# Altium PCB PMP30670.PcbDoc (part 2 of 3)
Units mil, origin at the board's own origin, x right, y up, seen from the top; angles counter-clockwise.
Board outline 5900 x 3950 mil, 4 copper layers (Top Layer, GND, Signal Layer, Bottom Layer), stack 79.834 mil thick; 198 components, 106 nets, 638 pads, 723 vias.
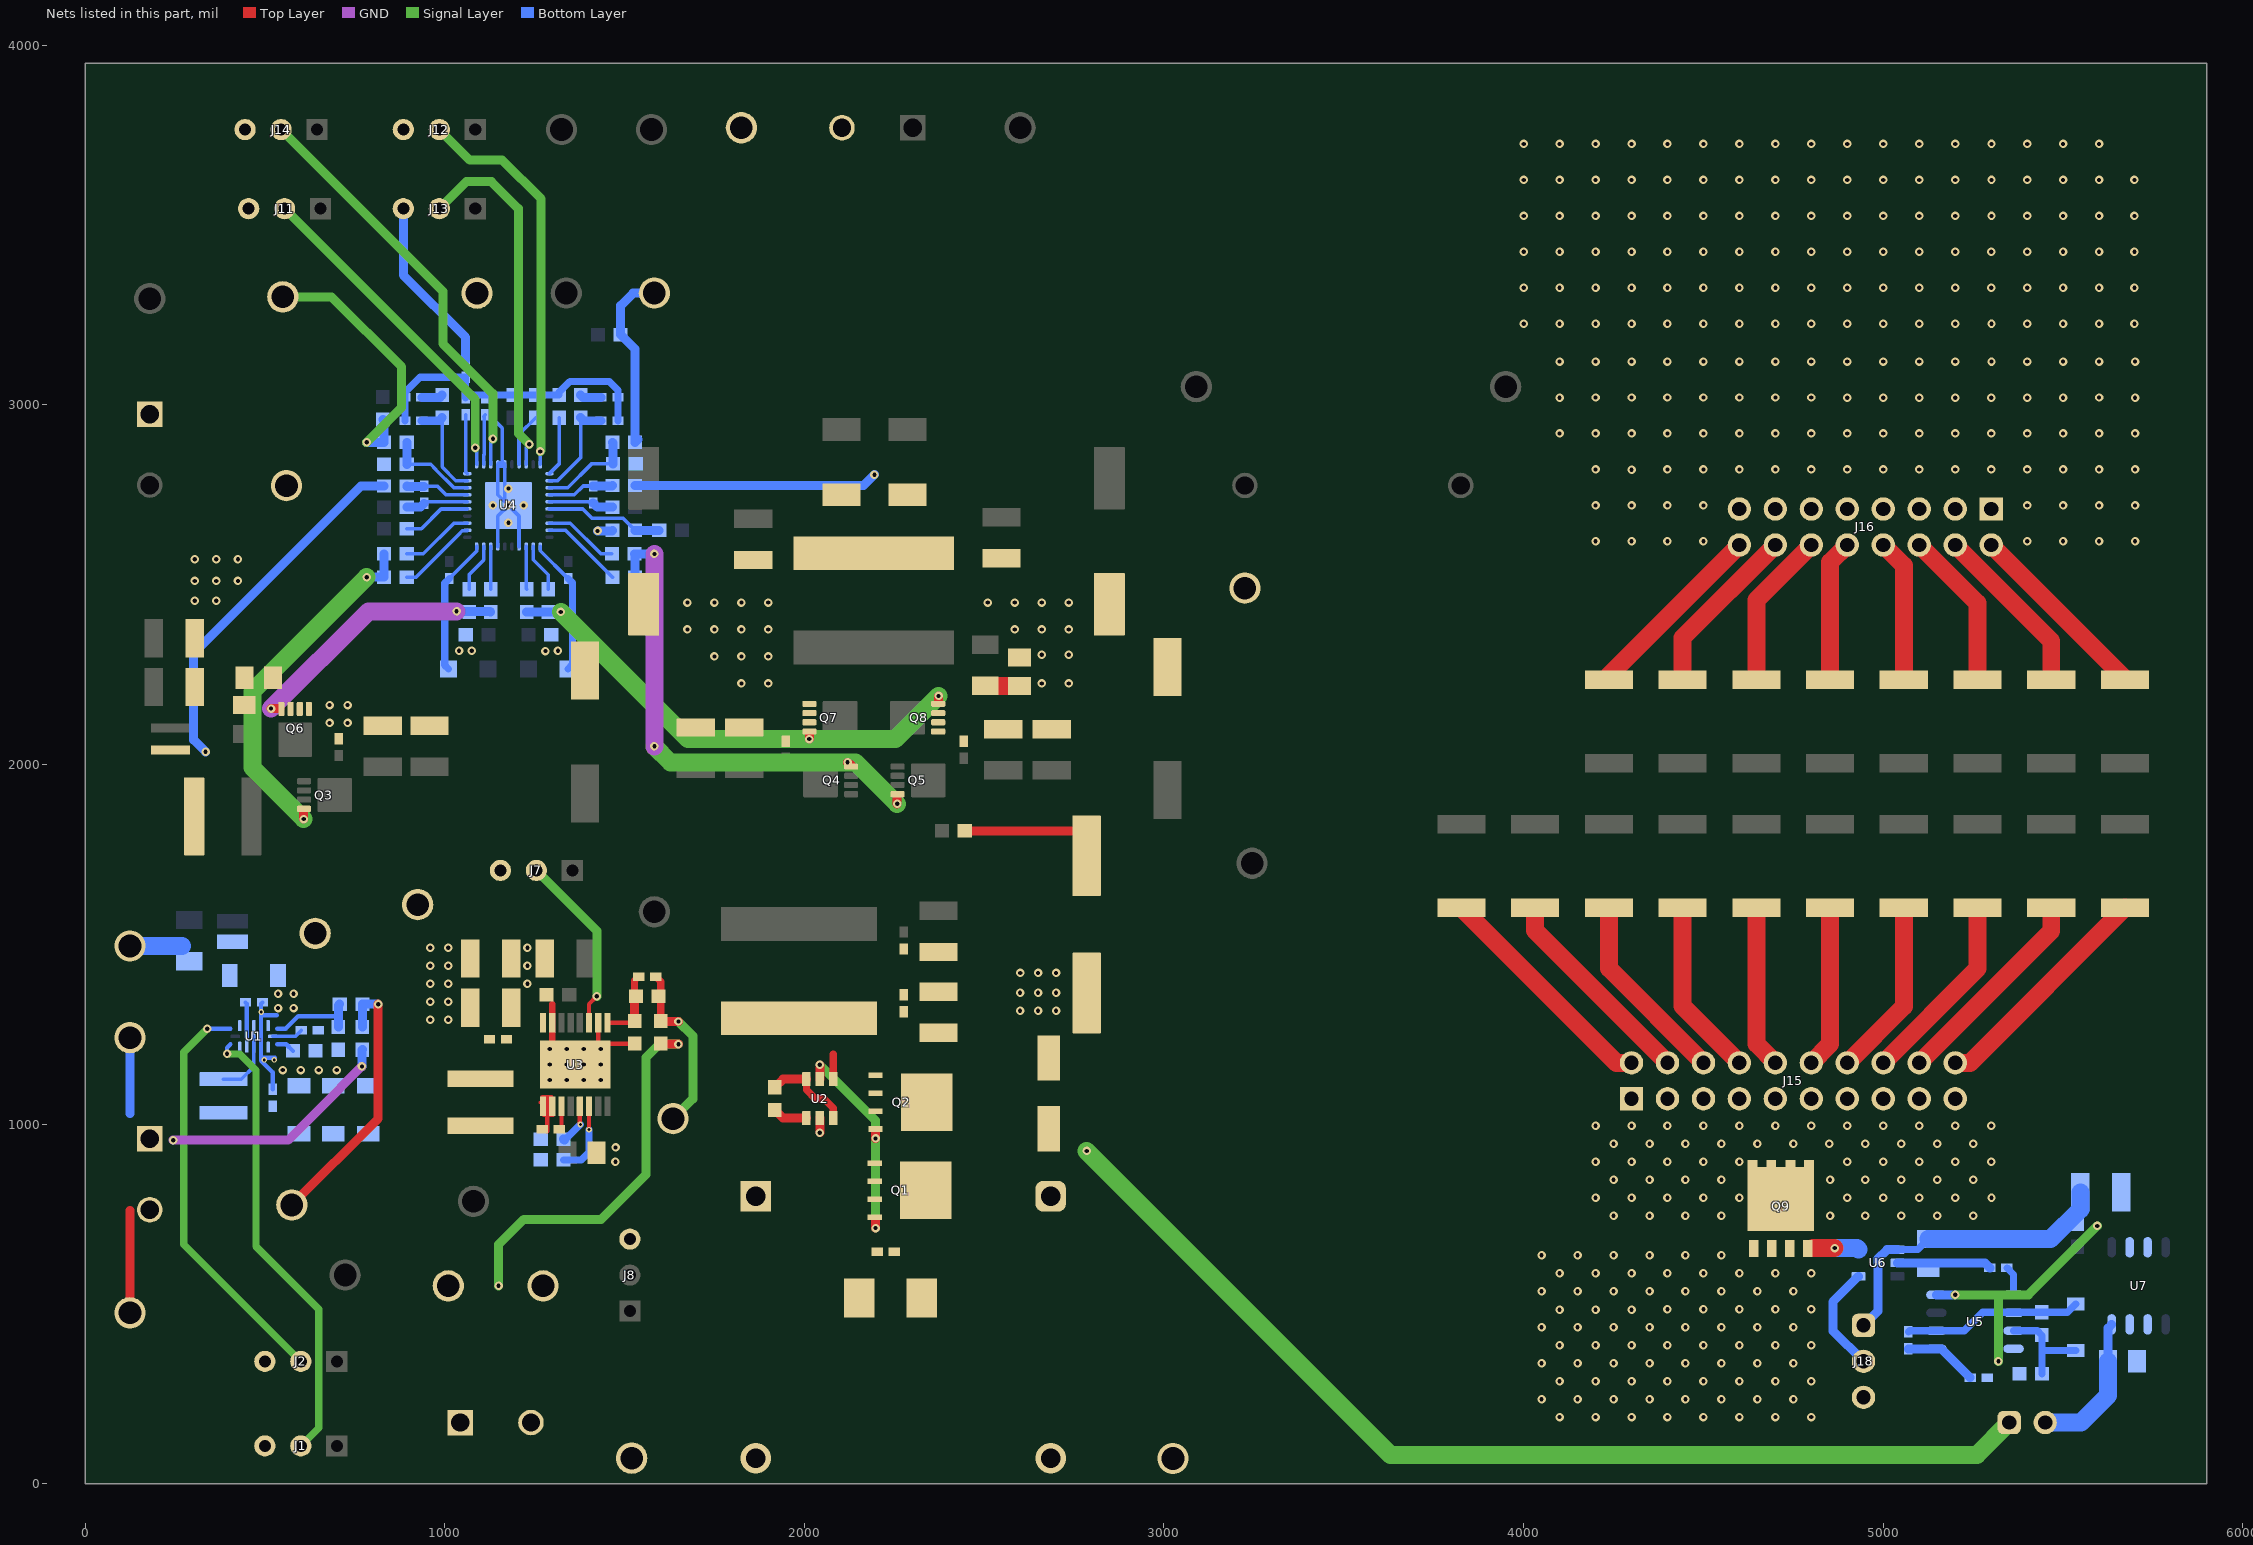
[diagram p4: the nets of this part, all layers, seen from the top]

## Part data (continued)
C40 C42: library part CMP-0008253-2, "CAP, CERM, 2200 pF, 250 V, +/- 10%, X7R, 0805", Cap_Case=0805, Manufacturer=MuRata, Supplier Part Number 1=490-3529-1-ND, TempCo=X7R, Tolerance_%=10%, Value1=Unknown, Value2=250V, ValueDisplayed=2200pF
C43: library part CMP-0007373-4, "CAP, CERM, 0.47 uF, 10 V, +/- 10%, X7R, 0603", Cap_Case=0603, Manufacturer=MuRata, Supplier Part Number 1=GRM188R71A474KA61D-ND, TempCo=X7R, Tolerance_%=10%, Value1=Unknown, Value2=10V, ValueDisplayed=0.47uF
C44 C45 C46: library part CMP-0007499-4, "CAP, CERM, 2.2 uF, 16 V, +/- 10%, X7R, 0603", Cap_Case=0603, Manufacturer=MuRata, Supplier Part Number 1=81-GRM188Z71C225KE3D, TempCo=X7R, Tolerance_%=10%, Value1=Unknown, Value2=16V, ValueDisplayed=2.2uF
C47 C48: library part CMP-0006641-2, "CAP, CERM, 0.1 uF, 16 V, +/- 10%, X7R, 0402", Cap_Case=0402, Manufacturer=MuRata, Supplier Part Number 1=490-3261-1-ND, TempCo=X7R, Tolerance_%=10%, Value1=Unknown, Value2=16V, ValueDisplayed=0.1uF
C49 C50: library part CMP-0006704-2, "CAP, CERM, 2200 pF, 100 V, +/- 10%, X7R, 0402", Cap_Case=0402, Manufacturer=MuRata, Supplier Part Number 1=GRM155R72A222KA01D-ND, TempCo=X7R, Tolerance_%=10%, Value1=Unknown, Value2=100V, ValueDisplayed=2200pF
C51: library part CMP-0006410-2, "CAP, CERM, 100 pF, 50 V, +/- 5%, C0G/NP0, 0402", Cap_Case=0402, Manufacturer=MuRata, Supplier Part Number 1=81-GRM1555C1H101JA1D, TempCo=C0G/NP0, Tolerance_%=5%, Value1=Unknown, Value2=50V, ValueDisplayed=100pF
C52: library part CMP-0006632-2, "CAP, CERM, 0.033 uF, 10 V, +/- 10%, X7R, 0402", Cap_Case=0402, Manufacturer=MuRata, Supplier Part Number 1=490-1315-1-ND, TempCo=X7R, Tolerance_%=10%, Value1=Unknown, Value2=10V, ValueDisplayed=0.033uF
C53: library part CMP-0006636-2, "CAP, CERM, 0.068 uF, 10 V, +/- 10%, X7R, 0402", Cap_Case=0402, Manufacturer=MuRata, Supplier Part Number 1=GRM155R71A683KA01D-ND, TempCo=X7R, Tolerance_%=10%, Value1=Unknown, Value2=10V, ValueDisplayed=0.068uF
C54: library part CMP-0007371-4, "CAP, CERM, 0.33 uF, 10 V, +/- 10%, X7R, 0603", Cap_Case=0603, Manufacturer=MuRata, Supplier Part Number 1=GRM188R71A334KA61D-ND, TempCo=X7R, Tolerance_%=10%, Value1=Unknown, Value2=10V, ValueDisplayed=0.33uF
C55: library part CMP-0006691-2, "CAP, CERM, 470 pF, 50 V, +/- 10%, X7R, 0402", Cap_Case=0402, Manufacturer=MuRata, Supplier Part Number 1=490-1300-1-ND, TempCo=X7R, Tolerance_%=10%, Value1=Unknown, Value2=50V, ValueDisplayed=470pF
C59: library part CMP-0008350-2, "CAP, CERM, 1 uF, 50 V, +/- 10%, X7R, 0805", Cap_Case=0805, Manufacturer=MuRata, Supplier Part Number 1=490-4736-1-ND, TempCo=X7R, Tolerance_%=10%, Value1=Unknown, Value2=50V, ValueDisplayed=1uF
C60: library part CMP-0009223-2, "CAP, CERM, 22 uF, 16 V, +/- 20%, X7R, 1210", Cap_Case=1210, Manufacturer=MuRata, Supplier Part Number 1=490-4740-1-ND, TempCo=X7R, Tolerance_%=20%, Value1="0.003 ohm", Value2=16V, ValueDisplayed=22uF
C64: library part CMP-0008320-2, "CAP, CERM, 4.7 uF, 10 V, +/- 10%, X7R, 0805", Cap_Case=0805, Manufacturer=MuRata, Supplier Part Number 1=GRM21BR71A475KA73L-ND, TempCo=X7R, Tolerance_%=10%, Value1=Unknown, Value2=10V, ValueDisplayed=4.7uF
"CAUTION! HOT SURFACE!1": library part CMP-0074837-1, "IEC 61010-1 Hot Surface Warning"
D1: library part CMP-0005564-3, "Diode, TVS, Bi, 33 V, SMB", Manufacturer="Diodes Inc.", Value1=600W
D2 D3: library part CMP-0028377-2, "Diode, Schottky, 60 V, 1 A, SOD-123F", Manufacturer=Nexperia, Value1=1A, Value2=0.57V
D4: library part CMP-0076920-2, "Diode, Switching, 100 V, 0.15 A, SOD-123FL", Manufacturer=Vishay-Semiconductor, Value1=0.15A, Value2=1.2V
J1 J2 J7 J8 J11 J12 J13 J14: library part CMP-0055086-1, "Header, 100mil, 3x1, TH", Manufacturer=Mill-Max, Supplier Part Number 1=ED7203-ND
J3 J6 J9 J10: library part CMP-0054828-1, "Terminal Block, 5 mm, 2x1, Tin, TH", Manufacturer="Wurth Elektronik", Supplier Part Number 1=732-2026-ND
J4: library part CMP-0055403-2, "TEST SOCKET, PCB, 4MM, RED", Manufacturer=Hirschmann, Supplier Part Number 1=06WX5875
J5: library part CMP-0055402-3, "TEST SOCKET, PCB, 4MM, BLACK", Color=Black, Manufacturer=Hirschmann, Supplier Part Number 1=06WX5874
J15: library part CMP-0075421-2, "Header, 100mil, 10x2, Gold, TH", Color=Black, Current_A=6.3A, Manufacturer=Samtec, Supplier Part Number 1=SAM1028-10-ND, Voltage_V=550V
J16: library part CMP-0075418-1, "Header, 100mil, 8x2, Gold, TH", Color=Black, Current_A=6.3A, Manufacturer=Samtec, Supplier Part Number 1=SAM1028-08-ND, Voltage_V=550V
J17: library part CMP-0075405-2, "Header, 100mil, 2x1, Gold, TH", Color=Black, Current_A=6.3A, Manufacturer=Samtec, Supplier Part Number 1=SAM1029-02-ND, Voltage_V=550V
J18: library part CMP-0075407-2, "Header, 100mil, 3x1, Gold, TH", Color=Black, Current_A=6.3A, Manufacturer=Samtec, Supplier Part Number 1=SAM1029-03-ND, Voltage_V=550V
L1: library part CMP-0061169-1, "Inductor, Shielded, Composite, 200 nH, 2.8 A, 0.02 ohm, SMD", Manufacturer=Coilcraft, Value1="0.02 ohm", Value2=2.8A, ValueDisplayed=200nH
L2: library part CMP-0061081-2, "Inductor, Shielded, Composite, 560 nH, 11.3 A, 0.008 ohm, AEC-Q200 Grade 1, SMD", Manufacturer=Coilcraft, Value1="0.008 ohm", Value2=11.3A, ValueDisplayed=560nH
L3: library part CMP-0060965-1, "Inductor, Shielded, Composite, 4.7 uH, 14 A, 0.0098 ohm, AEC-Q200 Grade 1, SMD", Manufacturer=Coilcraft, Supplier Part Number 1=994-XAL1060-472MEB, Value1="0.0098 ohm", Value2=14A, ValueDisplayed=4.7uH
L4: library part CMP-0061001-2, "Inductor, Shielded, Composite, 2.2 µH, 9.2 A, 0.01 ohm, AEC-Q200 Grade 1, SMD", Manufacturer=Coilcraft, PartNumber=XAL5030-222MEB, Value1="0.01 ohm", Value2=9.2A, ValueDisplayed=2.2uH
L5: library part CMP-0061652-3, "Inductor, Shielded, Composite, 15 µH, 5.8 A, 0.04375 ohm, AEC-Q200 Grade 1, SMD", Manufacturer=Coilcraft, Value1="0.04375 ohm", Value2=5.8A, ValueDisplayed=15uH
L6: library part CMP-0060947-1, "Inductor, Shielded, Composite, 2.2 uH, 32 A, 0.00255 ohm, SMD", Manufacturer=Coilcraft, Supplier Part Number 1=994-XAL1010-222MEB, Value1="0.00255 ohm", Value2=32A, ValueDisplayed=2.2uH
Q1 Q2: library part CMP-0000880-1, "MOSFET, N-CH, 60 V, 30 A, AEC-Q101, PowerPAK_SO-8L", Alternate Manufacturer=None, Manufacturer=Vishay-Siliconix, Value1=0.01, Value2="18 nC"
Q3 Q4 Q5 Q6 Q7 Q8: library part CMP-0080660-1, "MOSFET, N-CH, 40 V, 40 A, AEC-Q101, SON-8", Alternate Manufacturer=None, Manufacturer="Infineon Technologies", PartNumber=IPZ40N04S5L4R8ATMA1, Supplier Part Number 1=IPZ40N04S5L4R8ATMA1CT-ND, Value1="0.0067 ohm", Value2="22 nC"
Q9: library part CMP-0000690-1, "MOSFET, N-CH, 40 V, 49 A, PG-TDSON-8", Alternate Manufacturer=None, Manufacturer="Infineon Technologies", Supplier Part Number 1="BSC093N04LS GCT-ND", Value1=0.013, Value2="18 nC"
R1: library part CMP-0018748-3, "RES, 0, 5%, 0.25 W, AEC-Q200 Grade 0, 1206", Manufacturer=Panasonic, Power_W=250mW, Supplier Part Number 1=P0.0ECT-ND, TempCo="600 ppm/C", Tolerance_%=5%, Value2=0.25W, Value_Code=0000, ValueDisplayed=DNP
R2 R7 R26 R27 R31 R32: library part CMP-0022448-4, "RES, 49.9, 1%, 0.1 W, AEC-Q200 Grade 0, 0603", Manufacturer=Vishay-Dale, Power_W=100mW, Supplier Part Number 1=541-49.9HCT-ND, TempCo="100 ppm/C", Tolerance_%=1%, Value2=0.1W, Value_Code=49R9, ValueDisplayed=49.9
R3: library part CMP-0022369-4, "RES, 39.2 k, 1%, 0.1 W, AEC-Q200 Grade 0, 0603", Manufacturer=Vishay-Dale, Power_W=100mW, Supplier Part Number 1=541-39.2KHCT-ND, TempCo="100 ppm/C", Tolerance_%=1%, Value2=0.1W, Value_Code=39k2, ValueDisplayed=39.2k
R4: library part CMP-0022665-4, "RES, 9.09 k, 1%, 0.1 W, AEC-Q200 Grade 0, 0603", Manufacturer=Vishay-Dale, Power_W=100mW, Supplier Part Number 1=541-9.09KHCT-ND, TempCo="100 ppm/C", Tolerance_%=1%, Value2=0.1W, Value_Code=9k09, ValueDisplayed=9.09k
R5: library part CMP-0022438-4, "RES, 47.0 k, 1%, 0.1 W, AEC-Q200 Grade 0, 0603", Manufacturer=Vishay-Dale, Power_W=100mW, Supplier Part Number 1=541-47.0KHCT-ND, TempCo="100 ppm/C", Tolerance_%=1%, Value2=0.1W, Value_Code=47k0, ValueDisplayed=47.0k
R6: library part CMP-0022722-1, "RES, 0.12, 1%, 0.1 W, 0603", Manufacturer=Panasonic, Power_W=100mW, Supplier Part Number 1=P.12AJCT-ND, TempCo="300 ppm/C", Tolerance_%=1%, Value2=0.1W, Value_Code=R120, ValueDisplayed=0.12
R8: library part CMP-0022434-4, "RES, 46.4 k, 1%, 0.1 W, AEC-Q200 Grade 0, 0603", Manufacturer=Vishay-Dale, Power_W=100mW, Supplier Part Number 1=541-46.4KHCT-ND, TempCo="100 ppm/C", Tolerance_%=1%, Value2=0.1W, Value_Code=46k4, ValueDisplayed=46.4k
R9: library part CMP-0022602-4, "RES, 7.68 k, 1%, 0.1 W, AEC-Q200 Grade 0, 0603", Manufacturer=Vishay-Dale, Power_W=100mW, Supplier Part Number 1=541-7.68KHCT-ND, TempCo="100 ppm/C", Tolerance_%=1%, Value2=0.1W, Value_Code=7k68, ValueDisplayed=7.68k
R10 R37 R38: library part CMP-0021998-4, "RES, 10.0 k, 1%, 0.1 W, AEC-Q200 Grade 0, 0603", Manufacturer=Vishay-Dale, Power_W=100mW, Supplier Part Number 1=541-10.0KHCT-ND, TempCo="100 ppm/C", Tolerance_%=1%, Value2=0.1W, Value_Code=10k0, ValueDisplayed=10.0k
R11: library part CMP-0022204-4, "RES, 20.0 k, 1%, 0.1 W, AEC-Q200 Grade 0, 0603", Manufacturer=Vishay-Dale, Power_W=100mW, Supplier Part Number 1=541-20.0KHCT-ND, TempCo="100 ppm/C", Tolerance_%=1%, Value2=0.1W, Value_Code=20k0, ValueDisplayed=20.0k
R12: library part CMP-0015211-2, "RES, 0.013, 1%, 1 W, 0612", Manufacturer="Susumu Co Ltd", Power_W=1W, Supplier Part Number 1=PRL1632.013FCT-ND, TempCo="200 ppm/C", Tolerance_%=1%, Value_Code=R013, ValueDisplayed=0.013
R13 R15: library part CMP-0016512-2, "RES, 0.005, 1%, 1.5 W, 2010", Manufacturer="Stackpole Electronics Inc", Power_W=1.5W, Supplier Part Number 1=CSNL2010FT5L00CT-ND, TempCo="50 ppm/C", Tolerance_%=1%, Value_Code=5L000, ValueDisplayed=0.005
R14: library part CMP-0020487-2, "RES, 1.0, 5%, 0.125 W, 0805", Manufacturer=Vishay-Dale, Power_W=125mW, Supplier Part Number 1=541-1.0ACT-ND, TempCo="200 ppm/C", Tolerance_%=5%, Value2=0.125W, Value_Code=1R00, ValueDisplayed=DNP
R16: library part CMP-0016745-3, "RES, 1.00, 1%, 0.25 W, AEC-Q200 Grade 0, 1206", Manufacturer=Vishay-Dale, Power_W=250mW, Supplier Part Number 1=53K1855, TempCo="100 ppm/C", Tolerance_%=1%, Value2=0.25W, Value_Code=1R00, ValueDisplayed=DNP
R17: library part CMP-0022170-4, "RES, 1.00, 1%, 0.1 W, AEC-Q200 Grade 0, 0603", Manufacturer=Vishay-Dale, Power_W=100mW, Supplier Part Number 1=52K8059, TempCo="100 ppm/C", Tolerance_%=1%, Value2=0.1W, Value_Code=1R00, ValueDisplayed=1.00
R18 R19 R20 R21 R22 R23 R24 R25 R28 R29 R30: library part CMP-0025874-1, "RES, 0, 5%, 0.1 W, 0603", Manufacturer=Panasonic, Power_W=100mW, Supplier Part Number 1=P0.0GCT-ND, TempCo="600 ppm/C", Tolerance_%=5%, Value2=0.1W, Value_Code=0000, ValueDisplayed=0
R33: library part CMP-0022585-4, "RES, 73.2 k, 1%, 0.1 W, AEC-Q200 Grade 0, 0603", Manufacturer=Vishay-Dale, Power_W=100mW, Supplier Part Number 1=541-73.2KHCT-ND, TempCo="100 ppm/C", Tolerance_%=1%, Value2=0.1W, Value_Code=73k2, ValueDisplayed=73.2k
R34: library part CMP-0022430-4, "RES, 45.3 k, 1%, 0.1 W, AEC-Q200 Grade 0, 0603", Manufacturer=Vishay-Dale, Power_W=100mW, Supplier Part Number 1=541-45.3KHCT-ND, TempCo="100 ppm/C", Tolerance_%=1%, Value2=0.1W, Value_Code=45k3, ValueDisplayed=45.3k
R35: library part CMP-0022515-4, "RES, 5.90 k, 1%, 0.1 W, AEC-Q200 Grade 0, 0603", Manufacturer=Vishay-Dale, Power_W=100mW, Supplier Part Number 1=541-5.90KHCT-ND, TempCo="100 ppm/C", Tolerance_%=1%, Value2=0.1W, Value_Code=5k90, ValueDisplayed=5.90k
R36: library part CMP-0022044-4, "RES, 13.7 k, 1%, 0.1 W, AEC-Q200 Grade 0, 0603", Manufacturer=Vishay-Dale, Power_W=100mW, Supplier Part Number 1=541-13.7KHCT-ND, TempCo="100 ppm/C", Tolerance_%=1%, Value2=0.1W, Value_Code=13k7, ValueDisplayed=13.7k
R39: library part CMP-0022494-4, "RES, 54.9 k, 1%, 0.1 W, AEC-Q200 Grade 0, 0603", Manufacturer=Vishay-Dale, Power_W=100mW, Supplier Part Number 1=541-54.9KHCT-ND, TempCo="100 ppm/C", Tolerance_%=1%, Value2=0.1W, Value_Code=54k9, ValueDisplayed=54.9k
R40: library part CMP-0014307-3, "RES, 0.01, 1%, 3 W, 15.2x1.0x25.4", Manufacturer="TT Electronics/IRC", Power_W=3W, Supplier Part Number 1=989-1088-ND, TempCo="20 ppm/C", Tolerance_%=1%, Value_Code=R010, ValueDisplayed=0.01
R41 R42 R43 R44 R45 R46 R47 R48 R49 R50: library part CMP-0015940-2, "RES, 30, 5%, 1 W, AEC-Q200 Grade 0, 2512", Manufacturer=Vishay-Dale, Power_W=1W, Supplier Part Number 1=541-30XCT-ND, TempCo="200 ppm/C", Tolerance_%=5%, Value_Code=30R0, ValueDisplayed=30
R51 R52 R53 R54 R55 R56 R57 R58: library part CMP-0015453-3, "RES, 12.1, 1%, 1 W, AEC-Q200 Grade 0, 2512", Manufacturer=Vishay-Dale, Power_W=1W, Supplier Part Number 1=541-12.1AFCT-ND, TempCo="100 ppm/C", Tolerance_%=1%, Value_Code=12R1, ValueDisplayed=12.1
R59 R60: library part CMP-0022581-4, "RES, 71.5 k, 1%, 0.1 W, AEC-Q200 Grade 0, 0603", Manufacturer=Vishay-Dale, Power_W=100mW, Supplier Part Number 1=541-71.5KHCT-ND, TempCo="100 ppm/C", Tolerance_%=1%, Value2=0.1W, Value_Code=71k5, ValueDisplayed=71.5k
R61: library part CMP-0025743-1, "RES, 1.0, 5%, 0.1 W, 0603", Manufacturer=Vishay-Dale, Power_W=100mW, Supplier Part Number 1=541-1.0GCT-ND, TempCo="200 ppm/C", Tolerance_%=5%, Value2=0.1W, Value_Code=1R00, ValueDisplayed=1.0
TP1 TP2 TP6 TP9 TP10 TP15 TP17 TP19 TP20: library part CMP-0055147-1, "Test Point, Multipurpose, Red, TH", Color=Red, Manufacturer=Keystone, Supplier Part Number 1=36-5010-ND
TP3 TP7 TP8 TP11 TP14 TP16 TP18 TP25 TP26: library part CMP-0055148-1, "Test Point, Multipurpose, Black, TH", Color=Black, Manufacturer=Keystone, Supplier Part Number 1=36-5011-ND
TP4 TP12 TP23 TP24: library part CMP-0055151-1, "Test Point, Multipurpose, Yellow, TH", Color=Yellow, Manufacturer=Keystone, Supplier Part Number 1=36-5014-ND
TP5 TP13 TP21 TP22: library part CMP-0055149-1, "Test Point, Multipurpose, White, TH", Color=White, Manufacturer=Keystone, Supplier Part Number 1=36-5012-ND
TP27 TP28: library part CMP-0055150-1, "Test Point, Multipurpose, Orange, TH", Color=Orange, Manufacturer=Keystone, Supplier Part Number 1=36-5013-ND
U1: library part CMP-0082642-1, "Automotive Low Input Voltage, Adjustable-Frequency Step-down Converter, RWY0009A (VQFN-HR-9)", Alternate Manufacturer="Texas Instruments", Operating Temperature Range="-40 to 150 C", Rating=Automotive
U2: library part CMP-0013281-4, "Low Iq Always ON Smart Diode Controller, DBV0006A (SOT-23-6)", Alternate Manufacturer="Texas Instruments", Alternate PartNumber=LM74700QDBVTQ1
U3: library part CMP-0080079-4, "3.5-V to 36-V, 3.5-A Synchronous Step-Down Voltage Regulator with Spread Spectrum, PWP0016D (TSSOP-16)", Alternate Manufacturer="Texas Instruments", Rating=Automotive
U4: library part CMP-0079128-2, "3.5-V to 65-V Low IQ, Dual Synchronous Buck DC-DC Controller, RWG0040A (VQFNP-40)", Alternate Manufacturer="Texas Instruments", Alternate PartNumber=LM5143QRWGTQ1, Operating Temperature Range="-40 to 125 C", Rating=Automotive
U5: library part CMP-0068883-1, "CMOS Timer, 8-pin Narrow SOIC, Pb-Free", Manufacturer="Texas Instruments", PackageTopMarking=NSZXTT*LMC*555CM, PowerWise=N
U6: library part CMP-0066947-1, "4A/4A Single Channel High-speed Low-side Gate Driver, DBV0005A (SOT-23-5)", Alternate Manufacturer="Texas Instruments", Alternate PartNumber=UCC27517DBVT
U7: library part CMP-0035296-1, "Single Output LDO, 150 mA, Fixed 5 V Output, 6 to 26 V Input, with Low IQ, 8-pin SOIC (D), 0 to 125 degC, Green (RoHS & no Sb/Br)", Manufacturer="Texas Instruments", Rating=Catalog

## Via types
v1: diameter 23.62, hole 11.81, Top Layer to Bottom Layer, tented both sides, 701 vias
v2: diameter 23.62, hole 11.81, Top Layer to Bottom Layer, 11 vias
v3: diameter 15.75, hole 7.87, Top Layer to Bottom Layer, tented both sides, 7 vias
v4: diameter 196.85, hole 118.11, Top Layer to Bottom Layer, 4 vias

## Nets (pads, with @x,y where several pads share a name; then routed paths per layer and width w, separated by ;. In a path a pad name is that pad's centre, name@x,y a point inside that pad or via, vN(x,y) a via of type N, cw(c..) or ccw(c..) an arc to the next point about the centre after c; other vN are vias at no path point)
1V1_SINGLE_BUCK: C1.1 C2.1 C3.1 C4.1 J3.1 L2.2 R2.2 TP1.1 | length 869
  GND w25: v1(245,955) 565,955 650,1040 v1(770,1160)
  Bottom Layer w20: v1(770,1160) v1@771.14,1161.14
  Bottom Layer w25: 125,1029.58 TP1.1@125,1240 ; v1(770,1160) 770,1205.43 R2.2@771.14,1206.57
3V3_SINGLE_BUCK: C19.1 C20.1 C21.1 J6.1 L4.2 R7.2 TP10.1 | length 1086.1
  Top Layer w25: R7.2@1600.67,1223.51 1602.33,1221.85 v1(1650,1221.85)
  Signal Layer w25: v1(1150,550) 1150,665 1220,735 1435,735 1559.44,859.44 1559.44,1184.44 1596.85,1221.85 v1(1650,1221.85)
  other v1: 960,1290 1010,1290 960,1340 1010,1340 960,1390 1010,1390 960,1440 1010,1440 960,1490 1010,1490
CS1_DUAL_BUCK: L5.1 R12.2 R26.2 | length 1009.4
  Bottom Layer w25: v1(335,2035) 302.13,2067.87 302.13,2308.62 767.49,2773.98 R26.2@831.57,2773.98
CS2_DUAL_BUCK: L6.2 R13.1 R15.1 R27.1 | length 677.9
  Bottom Layer w25: R27.1@1529.57,2775.35 2165,2775.35 v1(2195,2805.35)
DEMB_DUAL_BUCK: J14.2 U4.33 | length 1177.7
  Signal Layer w25: J14.2@545,3765 995,3315 995,3170 1134.33,3030.67 v1(1134.33,2905)
  Bottom Layer w10: U4.33@1128.03,2834.06 1128.03,2898.7 v1(1134.33,2905)
DITH_DUAL_BUCK: J13.2 U4.38 | length 1009
  Signal Layer w25: J13.2@985,3545 1060,3620 1130,3620 1205,3545 1205,2920 v1(1235,2890)
  Bottom Layer w10: U4.38@1226.46,2834.06 1226.46,2881.46 v1(1235,2890)
EN1_DUAL_BUCK: J11.2 U4.31 | length 932
  Signal Layer w25: J11.2@555,3545 1085,3015 v1(1085,2880)
  Bottom Layer w10: v1(1085,2880) 1088.66,2876.34 U4.31@1088.66,2834.06
EN2_DUAL_BUCK: J12.2 U4.40 | length 1101.7
  Signal Layer w25: J12.2@985,3765 1070,3680 1160,3680 1267.87,3572.13 1267.87,2872.05 v1(1265.83,2870)
  Bottom Layer w10: U4.40@1265.83,2834.06 v1(1265.83,2870)
EN_1V1_BUCK: J1.2 U1.8 | length 1267.7
  Signal Layer w20: v1(395,1195) 430,1195 475,1150 475,660 650,485 650,155 J1.2@600,105
  Bottom Layer w12: v1(395,1195) 395,1212.13 404.69,1221.81
EN_3V3_BUCK: J7.2 U3.11 | length 502.1
  Top Layer w12: U3.11@1401.46,1281.5 1401.46,1333.39 v1(1423.07,1355)
  Signal Layer w25: J7.2@1255,1705 1423.07,1536.93 v1(1423.07,1355)
FB1_DUAL_BUCK: R33.1 R37.2 U4.28 | length 256.9
  Bottom Layer w10: R37.2@894.57,2834.06 960.94,2834.06 975.2,2819.8 975.2,2819.53 1023.82,2770.91 1024.09,2770.91 1025.91,2769.09 U4.28@1063.07,2769.09
  Bottom Layer w25: R37.2@894.57,2834.06 R33.1@894.57,2895.35
FB2_DUAL_BUCK: R34.1 R38.2 U4.3 | length 264.7
  Bottom Layer w10: U4.3@1291.42,2769.09 1341.81,2769.09 1408.07,2835.35 R38.2@1468.07,2835.35
  Bottom Layer w25: R34.1@1466.57,2895.35 1468.07,2893.86 R38.2@1468.07,2835.35
GND: C1.2 C2.2 C3.2 C4.2 C5.2 C6.2 C7.2 C8.2 C10.2 C11.2 C12.2 C13.2 C14.2 C15.1 C17.2 C18.2 C19.2 C20.2 C21.2 C23.2 C24.2 C25.2 C26.2 C27.2 C28.2 C29.2 C30.2 C31.2 C32.2 C33.2 C34.2 C35.2 C36.2 C37.1 C38.2 C39.2 C40.2 C41.1 C42.2 C43.1 C44.2 C45.2 C46.2 C51.2 C52.2 C53.2 C54.2 C55.2 C56.2 C57.2 C58.2 C59.2 C60.2 C61.2 C62.2 C63.2 C64.2 D1.1 J1.3 J2.3 J3.2 J5.1 J5.2 J6.2 J7.3 J8.3 J9.1 J10.2 J11.3 J12.3 J14.3 J16.1 J16.3 J16.5 J16.7 J16.9 J16.11 J16.13 J16.15 J18.3 Q6.1 Q6.2 Q6.3 Q7.1 Q7.2 Q7.3 Q8.1 Q8.2 Q8.3 Q9.1 Q9.2 Q9.3 R4.1 R5.1 R9.1 R10.1 R11.1 R37.1 R38.1 R39.1 TP3.1 TP7.1 TP8.1 TP11.1 TP14.1 TP16.1 TP18.1 TP25.1 TP26.1 U1.4@489.33,1243.46 U2.2 U3.10 U3.15 U3.16 U3.17@1363.07,1165.35 U4.14 U4.17 U4.34 U4.35 U4.41 U5.1 U6.2 U7.2 U7.3 U7.6 U7.7 | length 3142.9
  Top Layer w12: U3.17@1363.07,1165.35 U3.17@1421.22,1223.51 ; U3.10@1427.05,1281.5 1427.05,1229.33 U3.17@1421.22,1223.51 ; R11.1@1528.07,1223.51 U3.17@1421.22,1223.51
  Top Layer w17.5: U3.17@1298.99,1230 1299.04,1281.5 1299.09,1333.6
  Top Layer w25: TP7.1@125,475 125,760 ; U3.17@1363.07,1165.35 v2(1386.69,1165.35) v1(1433.94,1165.35) ; v1(2043.07,975.71) U2.2@2043.07,1016.57
  Bottom Layer w10: 1140,3018.98 1140,2955 1160,2935 1160,2841.46 ; U4.17@1147.72,2605.71 1147.72,2690.35 v2(1177.24,2719.88) ; U4.34@1147.72,2834.06 1147.72,2749.41 U4.41@1167.4,2729.72 ; U4.35@1167.4,2834.06 U4.41@1167.4,2729.72 ; U4.14@1206.77,2605.71 1206.77,2690.35 v2(1177.24,2719.88) ; U4.41@1167.4,2729.72 v2(1177.24,2719.88)
  Bottom Layer w12: C6.2@493.27,1338.07 489.33,1334.13 489.33,1300 ; C1.2@521.81,1096.69 521.81,1143.54 489.33,1176.02 489.33,1185 ; v3@528.24,1184.32 490.02,1184.32 489.33,1185 ; 533.43,1302.61 491.94,1302.61 489.33,1300 ; 489.33,1185 U1.4@489.33,1243.46 489.33,1300
  Bottom Layer w20: C51.2@889.45,2955.35 C56.2@889.45,3020.35 889.45,3034.45 931.38,3076.38 C58.2@1058.07,3076.38 C52.2@1058.07,3018.98 1065.94,3026.85 C54.2@1318.07,3026.85 1318.07,3034.45 1348.03,3064.41 1457.6,3064.41 1481.69,3040.31 C57.2@1481.69,3020.35 C55.2@1481.69,2955.35 ; 1153,2834.06 1162,2834.06
  Bottom Layer w25: v1(1425,2649.09) 1465.32,2649.09 C44.2@1466.57,2650.35 ; U6.2@5039.13,613.62 5282.76,613.62 C63.2@5296.38,600 ; C62.2@5070,374.88 5147.6,374.88 U5.1@5147.72,375 5161.38,375 C61.2@5241.38,295
  other v1: 4100,185.16 4200,185 4300,185 4400,185 4500,185 4600.04,185 4700,185.16 4800,185.16 4050,235 4150,235 4250,235 4350,235 4450,235 4550,235 4650,235 4750,235 4100,285 4200,285 4300,285 4400,285 4500,285 4600.04,285 4700,285 4800,285 4050,335 4150,335 4250,335 4350,335 4450,335 4550,335 4650,335 4750,335 4100,385 4200,385 4300,385 4400,385 4500,385 4600.04,385 4700,385 4800,385 4050,435 4150,435 4250,435 4350,435 4450,435 4550,435 4650,435 4750,435 4100,483.53 4200,483.53 4300,483.53 4400,485 4500,485 4600.04,485 4700,485 4800,485 4050,535 4150,535 4250,535 4350,535 4450,535 4550,535 4650,535 4750,535 4100,585 4200,585 4300,585 4400,585 4500,585 4600,585 4700,585 4800,585 4050,634.83 4150,634.83 4250,635 4350,635 4450,635 4550,635 1474.84,895 1475,935 1292.2,1122.05 1433.94,1122.05 550,1150 600,1150 650,1150 700,1150 1292.2,1165.35 1292.2,1208.66 1433.94,1208.66 2600,1315 2650,1315 2700,1315 536.57,1322.52 580,1322.52 536.57,1362 580,1362 2600,1365 2650,1365 2700,1365 1230,1390 2600.69,1420 2650,1420 2700,1420 1230,1440 1230,1490 680,2115 730,2115 680,2165 730,2165 1825,2225 1900,2225 2660,2225 2735.36,2225 1750,2300 1825,2300 1900,2300 2660,2305 2735.36,2305 1280,2315 1040,2315.8 1075,2315.8 1315,2315.8 1675,2375 1750,2375 1825,2375 1900,2375 2585,2375 2660,2375 2735,2375 1675,2450 1750,2450 1825,2450 1900,2450 2510,2450 2585,2450 2660,2450 2735,2450 305,2455 365,2455 305,2510 365,2510 425,2510 305,2570 365,2570 425,2570 4200,2620 4300,2620 4400,2620 4500,2620 5400,2620 5500,2620 5600,2620 5700,2620 4200,2720 4300,2719.88 4400,2720 4500,2720 5400,2720 5500,2719.88 5600,2720 5700,2719.88 4300,2819.41 4200,2820 4400,2820 4500,2820 4600,2820 4700,2820 4800,2820 4900,2820 5000,2820 5100,2820 5200,2820 5300,2820 5400,2820 5500,2820 5600,2820 5700,2820 4100,2920 4200,2920 4300,2920 4400,2920 4500,2920 4600,2920 4700,2920 4800,2920 4900,2920 5000,2920 5100,2920 5200,2920 5300,2920 5400,2920 5500,2920 5600,2920 5700,2920 4100,3018.98 4900,3018.98 5000,3018.98 5100,3018.98 5200,3018.98 5300,3018.98 5400,3018.98 5500,3018.98 5700,3018.98 4200,3020 4300,3020 4400,3020 4500,3020 4600.04,3020 4700,3020 4800,3020 5600,3020 4100,3120 4200,3120 4300,3120 4400,3120 4500,3120 4600.04,3120 4700,3120 4800,3120 4900,3120 5000,3120 5100,3120 5200,3120 5300.88,3120 5400,3120 5500,3120 5600,3120 5700,3120 4000,3225 4100,3225 4200,3225 4300,3225 4400,3225 4500,3225 4600,3225 4700,3225 4800,3225 4900,3225 5000,3225 5100,3225 5200,3225 5300.88,3225 5400,3225 5500,3225 5600,3225 5698.35,3225 4000,3325 4100,3325 4200,3325 4300,3325 4400,3325 4500,3325 4600.04,3325 4700,3325 4800,3325 4900,3325 5000,3325 5100,3325 5200,3325 5300,3325 5400,3325 5500,3325 5600,3325 5698.35,3325 4000,3425 4100,3425 4200,3425 4300,3425 4400,3425 4500,3425 4600,3425 4700,3425 4800,3425 4900,3425 5000,3425 5100,3425 5200,3425 5300,3425 5400,3425 5500,3425 5600,3425 5698.35,3425 4000,3525 4100,3525 4200,3525 4300,3525 4400,3525 4500,3525 4600,3525 4700,3525 4800,3525 4900,3525 5000,3525 5100,3525 5200,3525 5300.88,3525 5400,3525 5500,3525 5600,3525 5698.35,3525 4000,3625 4100,3625 4200,3625 4300,3625 4400,3625 4500,3625 4600,3625 4700,3625 4800,3625 4900,3625 5000,3625 5100,3625 5200,3625 5300.88,3625 5400,3625 5500,3625 5600,3625 5698.35,3625 4000,3725 4100,3725 4200,3725 4300,3725 4400,3725 4500,3725 4600.04,3725 4700,3725 4800,3725 4900,3725 5000,3725.09 5100,3725.09 5200,3725.09 5300.88,3725.09 5400,3725 5500,3725.09 5600,3725
  other v2: 1339.45,1122.05 1386.69,1122.05 1339.45,1165.35 1339.45,1208.66 1386.69,1208.66 1177.24,2671.97 1134.33,2719.88 1219.33,2719.88 1177.24,2766.97
  other v3: 498.28,1178.38 526.12,1178.38 490,1311.26
HS1_GD: Q3.4 R19.1 R21.1 | length 999.4
  Top Layer w25: v1(608.07,1847.76) Q3.4@608.07,1870
  Signal Layer w50: v1(608.07,1847.76) 465,1990.83 465,2202.28 v1(783.07,2520.35)
  Bottom Layer w25: v1(783.07,2520.35) R19.1@831.57,2520.35 R21.1@831.57,2585.35
HS2_GD: Q4.4 Q5.4 R20.2 R22.2 | length 1430
  Top Layer w25: v1(2120.16,2005.71) Q4.4@2130.16,2000 ; v1(2258.07,1890.35) Q5.4@2258.07,1912.46
  GND w50: v1(1583.07,2050) v1(1583.07,2585)
  Signal Layer w50: v1(1583.07,2050) 1627.36,2005.71 v1(2120.16,2005.71) 2142.72,2005.71 v1(2258.07,1890.35)
  Bottom Layer w25: R22.2@1528.07,2585.35 R22.2@1528.43,2585 ; R20.2@1529.57,2520.35 1529.57,2583.86 R22.2@1528.43,2585 ; v1(1583.07,2585) R22.2@1528.43,2585
KL30: C10.1 C12.1 C13.1 J17.1 L3.1 Q1.5 Q2.5 U2.4 | length 3022.4
  Top Layer w20: U2.4@2080.47,1124.84 2080.47,1195
  Signal Layer w50: v1(2785,925) 3630,80 5260,80 J17.1@5350,170
LS1_GD: Q6.4 R23.2 R25.2 | length 747.4
  Top Layer w25: v1(517.4,2155) Q6.4@541.56,2155
  GND w50: v1(517.4,2155) 787.76,2425.35 v1(1033.07,2425.35)
  Bottom Layer w25: v1(1033.07,2425.35) 1126.57,2425.35 R23.2@1128.07,2423.86
LS2_GD: Q7.4 Q8.4 R24.2 R28.2 | length 1372.4
  Top Layer w25: v1(2014.02,2070.35) Q7.4@2014.02,2083.62 ; Q8.4@2373.07,2172.34 v1(2373.07,2190.35)
  Signal Layer w50: v1(1323.07,2423.86) 1676.57,2070.35 v1(2014.02,2070.35) 2253.07,2070.35 v1(2373.07,2190.35)
  Bottom Layer w25: R24.2@1228.07,2423.86 R28.2@1288.07,2423.86 v1(1323.07,2423.86)
MODE_1V1_BUCK: J2.2 U1.1 | length 1151.4
  Signal Layer w20: v1(340,1265) 274.68,1199.68 274.68,665.32 J2.2@600,340
  Bottom Layer w12: v1(340,1265) 404.57,1265
NetC5_1: C5.1 C6.1 L1.2 R1.2 TP2.1 U1.2@449.96,1243.46 | length 241.2
  Bottom Layer w12: C6.1@446.02,1338.07 449.96,1334.13 U1.2@449.96,1243.46
  Bottom Layer w50: TP2.1@125,1495 270,1495
NetC7_1: C7.1 U1.6 | length 86.1
  Bottom Layer w10: U1.6@521.81,1243.46 584.29,1243.46 C7.1@601.02,1260.2
NetC8_1: C8.1 C9.2 D1.2 J4.1 J4.2 Q1.1 Q1.2 Q1.3 Q2.1 Q2.2 Q2.3 TP6.1 U2.3 U2.6 | length 250.5
  Top Layer w20: U2.6@2005.67,1124.84 2005.67,1095 2030.67,1070 2054.97,1070 2080.47,1044.5 U2.3@2080.47,1016.57
  Top Layer w25: C9.2@1918.07,1102.2 1940.71,1124.84 U2.6@2005.67,1124.84
NetC9_1: C9.1 U2.1 | length 97
  Top Layer w25: C9.1@1918.07,1039.21 1940.71,1016.57 U2.1@2005.67,1016.57
NetC15_2: C15.2 R6.1 | length 313.9
  Top Layer w25: R6.1@2446.06,1815.35 C15.2@2760,1815.35
NetC16_1: C16.1 U3.3 | length 66.7
  Top Layer w12: C16.1@1318.62,985 1324.69,991.06 U3.3@1324.69,1049.21
NetC16_2: C16.2 L4.1 U3.1 U3.2 | length 220.7
  Top Layer w12: U3.1@1267.2,1059.97 U3.2@1292.8,1059.97 ; U3.1@1271.38,1074.22 U3.2@1296.97,1074.22 ; U3.1@1273.4,1049.21 U3.2@1298.99,1049.21 ; U3.1@1273.5,1069.16 U3.2@1299.09,1069.16 ; U3.1@1275.08,1030 U3.2@1300.67,1030 ; U3.1@1275.08,1040 U3.2@1300.67,1040 ; U3.1@1275.5,1025 U3.2@1301.09,1025 ; C16.2@1285,980.03 1285,1021.57
NetC22_1: C22.1 R7.1 R8.2 TP12.1 | length 488.6
  Top Layer w20: C22.1@1586.69,1410 1600.67,1396.03 R7.1@1600.67,1286.5
  Top Layer w25: R7.1@1600.67,1286.5 1602.17,1285 v1(1650,1285)
  Signal Layer w25: TP12.1@1635,1015 1690,1070 1690,1245 v1(1650,1285)
NetC22_2: C22.2 R8.1 R11.2 U3.9 | length 205.7
  Top Layer w12: U3.9@1452.64,1281.5 1523.07,1281.5 R11.2@1528.07,1286.5
  Top Layer w20: R8.1@1528.07,1351.5 1528.07,1398.63 C22.2@1539.45,1410
  Top Layer w25: R11.2@1528.07,1286.5 R8.1@1528.07,1351.5
NetC40_1: C40.1 R14.1
NetC42_1: C42.1 R16.1 | length 95.3
  Top Layer w50: R16.1@2503.07,2218.27 2503.78,2217.56 C42.1@2598.07,2217.56
NetC44_1: C44.1 R17.1 U4.6 | length 329.9
  Bottom Layer w10: U4.6@1291.42,2710.04 1384,2710.04 1410.26,2683.78 1496.14,2683.78 C44.1@1529.57,2650.35
  Bottom Layer w25: C44.1@1529.57,2650.35 R17.1@1596.57,2650.35
NetC47_1: C47.1 D2.1 U4.20 | length 381.9
  Bottom Layer w10: C47.1@1013.07,2516.73 1088.66,2592.32 U4.20@1088.66,2605.71
  Bottom Layer w20: D2.1@1010.83,2265 1000,2275.83 1000,2503.66 C47.1@1013.07,2516.73
NetC48_1: C48.1 D3.1 U4.11 | length 382.5
  Bottom Layer w10: U4.11@1265.83,2605.71 1265.83,2593.98 C48.1@1343.07,2516.73
  Bottom Layer w20: C48.1@1343.07,2516.73 1355,2504.8 1355,2276.81 D3.1@1343.19,2265
NetC49_1: C49.1 R26.1 U4.27 | length 178.7
  Bottom Layer w10: C49.1@943.07,2773.03 980,2773.03 1003.62,2749.41 U4.27@1063.07,2749.41
  Bottom Layer w25: R26.1@894.57,2773.98 895.51,2773.03 C49.1@943.07,2773.03
NetC49_2: C49.2 R29.2 U4.26 | length 174.5
  Bottom Layer w10: C49.2@943.07,2725.79 947.01,2729.72 U4.26@1063.07,2729.72
  Bottom Layer w25: R29.2@894.57,2715.35 932.64,2715.35 C49.2@943.07,2725.79
NetC50_1: C50.1 R27.2 U4.4 | length 185.9
  Bottom Layer w10: U4.4@1291.42,2749.41 1360.32,2749.41 1384.88,2773.98 C50.1@1413.07,2773.98
  Bottom Layer w25: C50.1@1413.07,2773.98 1465.2,2773.98 R27.2@1466.57,2775.35
NetC50_2: C50.2 R30.1 U4.5 | length 181.1
  Bottom Layer w10: U4.5@1291.42,2729.72 1410.08,2729.72 C50.2@1413.07,2726.73
  Bottom Layer w25: C50.2@1413.07,2726.73 1424.45,2715.35 R30.1@1466.57,2715.35
NetC51_1: C51.1 R35.2 U4.29 | length 282.6
  Bottom Layer w10: R35.2@993.07,2963.86 993.07,2826.93 1031.22,2788.78 U4.29@1063.07,2788.78
  Bottom Layer w25: C51.1@936.69,2955.35 984.57,2955.35 R35.2@993.07,2963.86
NetC52_1: C52.1 U4.30 | length 165.3
  Bottom Layer w10: C52.1@1058.07,2971.73 1058.07,2813.46 U4.30@1063.07,2808.46
NetC53_1: C53.1 U4.32 | length 141.5
  Bottom Layer w10: U4.32@1108.35,2834.06 1108.35,2860.28 1109.68,2861.61 1109.68,2894.74 1109.65,2894.78 1109.65,2967.01 1108.35,2967.01 C53.1@1113.07,2971.73
NetC54_1: C54.1 U4.1 | length 166.4
  Bottom Layer w10: U4.1@1291.42,2808.46 1318.07,2835.12 C54.1@1318.07,2963.86
NetC55_1: C55.1 R36.2 U4.2 | length 284
  Bottom Layer w10: U4.2@1291.42,2788.78 1313.78,2788.78 1378.07,2853.07 R36.2@1378.07,2963.86
  Bottom Layer w25: R36.2@1378.07,2963.86 1386.57,2955.35 C55.1@1434.45,2955.35
NetC56_1: C56.1 R35.1 | length 59.1
  Bottom Layer w25: C56.1@936.69,3020.35 986.57,3020.35 R35.1@993.07,3026.85
NetC57_1: C57.1 R36.1 | length 59.1
  Bottom Layer w25: R36.1@1378.07,3026.85 1384.57,3020.35 C57.1@1434.45,3020.35
NetC58_1: C58.1 J13.3 | length 493.1
  Bottom Layer w25: J13.3@885,3545 885,3360.35 1058.07,3187.28 C58.1@1058.07,3123.62
NetC59_1: C59.1 J17.2 U7.8 | length 407.9
  Bottom Layer w25: C59.1@5625,340 5625,432.72 U7.8@5635,442.72
  Bottom Layer w50: J17.2@5450,170 5550,170 5625,245 C59.1@5625,340
NetC60_1: C60.1 C61.1 C64.1 J18.1 R59.2 R61.2 U5.4 U5.8 U6.1 | length 1582.6
  Signal Layer w25: v1(5200,525) 5315,525 ; v1(5320,340) 5320,520 5315,525 ; v1(5595,716.5) 5403.5,525 5315,525
  Bottom Layer w20: U6.1@5039.13,651.02 5096.02,651.02 C64.1@5125,680
  Bottom Layer w25: J18.1@4945,440 4985,480 4985,625.35 5010.67,651.02 U6.1@5039.13,651.02 ; U5.4@5147.72,525 v1(5200,525)
  Bottom Layer w50: C64.1@5125,680 5465,680 5547.91,762.91 C60.1@5547.91,810
NetC62_1: C62.1 D4.1 R60.1 U5.2 U5.6 | length 497
  Bottom Layer w20: C62.1@5070,422.13 5072.87,425 U5.2@5147.72,425 5225,425 5276.5,476.5 R60.1@5440,476.5 5512.03,476.5 D4.1@5535,499.47
NetC63_1: C63.1 U5.5 | length 82.7
  Bottom Layer w20: C63.1@5343.62,600 5362.28,581.34 U5.5@5362.28,525
NetD4_2: D4.2 R59.1 R60.2 U5.7 | length 285.3
  Bottom Layer w20: U5.7@5362.28,425 5428.5,425 R60.2@5440,413.5 5441.5,412.01 5441.5,370 ; R59.1@5441.5,305 5441.5,370 ; D4.2@5535,370.53 5442.03,370.53 5441.5,370
NetJ15_1: J15.1 J15.3 J15.5 J15.7 J15.9 J15.11 J15.13 J15.15 J15.17 J15.19 Q9.5 Q9.6 Q9.7 Q9.8 Q9.9
  other v1: 4250,745 4350,745 4450,745 4550,745 4852,745 4950,745 5050,745 5150,745 5250,745 4200,795 4300,795 4400,795 4500,795 4600,795 4900,795 5000,795 5100,795 5200,795 5300.88,795 4250,845 4350,845 4450,845 4550,845 4852,845 4950,845 5050,845 5150,845 5250,845 4200,895 4300,895 4400,895 4500,895 4600,895 4900,895 5000,895 5100,895 5200,895 5300,895 4250,945 4350,945 4450,945 4550,945 4650,945 4750,945 4850,945 4950,945 5050,945 5150,945 5250,945 4200,995 4300,995 4400,995 4500,995 4600,995 4700,995 4800,995 4900,995 5000,995 5100,995 5200,995 5300,995
NetJ15_2: J15.2 R41.1 | length 651.5
  Top Layer w50: R41.1@3827,1601.06 4258.06,1170 J15.2@4300,1170
NetJ15_4: J15.4 R42.1 | length 583.5
  Top Layer w50: R42.1@4032,1601.06 4032,1538 J15.4@4400,1170
NetJ15_6: J15.6 R43.1 | length 540
  Top Layer w50: R43.1@4237,1601.06 4237,1433 J15.6@4500,1170
NetJ15_8: J15.8 R44.1 | length 496.5
  Top Layer w50: R44.1@4442,1601.06 4442,1328 J15.8@4600,1170
NetJ15_10: J15.10 R45.1 | length 453
  Top Layer w50: R45.1@4647,1601.06 4647,1223 J15.10@4700,1170
NetJ15_12: J15.12 R46.1 | length 452.6
  Top Layer w50: J15.12@4800,1170 4852,1222 R46.1@4852,1601.06
NetJ15_14: J15.14 R47.1 | length 496.1
  Top Layer w50: J15.14@4900,1170 5057,1327 R47.1@5057,1601.06
NetJ15_16: J15.16 R48.1 | length 539.6
  Top Layer w50: J15.16@5000,1170 5262,1432 R48.1@5262,1601.06
NetJ15_18: J15.18 R49.1 | length 583.1
  Top Layer w50: J15.18@5100,1170 5467,1537 R49.1@5467,1601.06
NetJ15_20: J15.20 R50.1 | length 650.6
  Top Layer w50: J15.20@5200,1170 5240.7,1170 R50.1@5672,1601.3
NetJ16_2: J16.2 R51.1 | length 528.9
  Top Layer w50: J16.2@5300,2610 5672,2238 R51.1@5672,2235.14
NetJ16_4: J16.4 R52.1 | length 485.5
  Top Layer w50: J16.4@5200,2610 5467,2343 R52.1@5467,2235.14
NetJ16_6: J16.6 R53.1 | length 442
  Top Layer w50: J16.6@5100,2610 5262,2448 R53.1@5262,2235.14
NetJ16_8: J16.8 R54.1 | length 398.5
  Top Layer w50: J16.8@5000,2610 5057,2553 R54.1@5057,2235.14
NetJ16_10: J16.10 R55.1 | length 394.7
  Top Layer w50: R55.1@4852,2235.14 4852,2562 J16.10@4900,2610
NetJ16_12: J16.12 R56.1 | length 438.2
  Top Layer w50: R56.1@4647,2235.14 4647,2457 J16.12@4800,2610
NetJ16_14: J16.14 R57.1 | length 481.7
  Top Layer w50: R57.1@4442,2235.14 4442,2352 J16.14@4700,2610
NetJ16_16: J16.16 R58.1 | length 525.2
  Top Layer w50: R58.1@4237,2235.14 4237,2247 J16.16@4600,2610
NetJ18_2: J18.2 U6.4 | length 300.8
  Bottom Layer w25: U6.4@4930.87,576.22 4860,505.35 4860,425 J18.2@4945,340
NetL2_1: L2.1 U1.3@469.65,1243.46 | length 183.3
  Bottom Layer w10: L2.1@384.65,1124.72 434.72,1124.72 469.65,1159.65 U1.3@469.65,1243.46
NetQ1_4: Q1.4 Q2.4 U2.5 | length 592.2
  Top Layer w25: U2.5@2043.07,1124.84 v1(2043.07,1164.65) ; v1(2198.07,710.71) 2198.07,730 ; v1(2198.07,960) 2198.07,975
  Signal Layer w25: v1(2043.07,1164.65) 2198.07,1009.65 v1(2198.07,960) v1(2198.07,710.71)
NetQ9_4: Q9.4 U6.5 | length 127.5
  Top Layer w50: 4805,655 v1(4865,655)
  Bottom Layer w50: v1(4865,655) 4926.89,655 U6.5@4930.87,651.02
NetR2_1: R2.1 R3.2 TP4.1 | length 765
  Top Layer w25: TP4.1@575,775 815,1015 v1(815,1333.19)
  Bottom Layer w25: R2.1@771.14,1269.57 R3.2@771.14,1333.07 771.26,1333.19 v1(815,1333.19)
NetR3_1: R3.1 R5.2 U1.5 | length 249.4
  Bottom Layer w12: 534.61,1265.12 557.95,1265.12 592.84,1300 704.65,1300
  Bottom Layer w25: R5.2@704.65,1269.57 704.65,1300 704.65,1329.57 R3.1@708.15,1333.07
NetR4_2: R4.2 U1.7 | length 51.3
  Bottom Layer w12: 534.61,1221.81 559.41,1221.81 R4.2@578.15,1203.07
NetR9_2: R9.2 U3.5 | length 123.5
  Top Layer w10: v3@1375.87,1000.06 v3(1377.27,998.66)
  Top Layer w12: v3@1375.87,1000.06 U3.5@1375.87,1049.21 U3.5@1378.72,1046.35
  Bottom Layer w20: R9.2@1330,958 1336.61,958 v3(1377.27,998.66)
  Bottom Layer w25: R9.2@1330,958 R9.2@1333,955
NetR10_2: R10.2 U3.6 | length 208.1
  Top Layer w12: v3(1401.46,984.38) U3.6@1401.46,1049.21
  Bottom Layer w20: R10.2@1330,900 1380,900 1401.46,921.46 v3(1401.46,984.38)
NetR18_2: R18.2 U4.25 | length 191.2
  Bottom Layer w10: R18.2@894.57,2655.35 935.35,2655.35 990.04,2710.04 U4.25@1063.07,2710.04
NetR19_2: R19.2 U4.22 | length 223.9
  Bottom Layer w10: R19.2@894.57,2520.35 920.35,2520.35 1038.39,2638.39 1038.39,2638.67 1048.81,2649.09 1063.07,2649.09 U4.22@1063.07,2650.98
NetR20_1: R20.1 U4.9 | length 229.3
  Bottom Layer w10: U4.9@1291.42,2650.98 1335.94,2650.98 R20.1@1466.57,2520.35
NetR21_2: R21.2 U4.23 | length 203.8
  Bottom Layer w10: R21.2@894.57,2585.35 940.35,2585.35 1025.67,2670.67 U4.23@1063.07,2670.67
NetR22_1: R22.1 U4.8 | length 209
  Bottom Layer w10: U4.8@1291.42,2670.67 1349.33,2670.67 1434.65,2585.35 R22.1@1465.08,2585.35
NetR23_1: R23.1 U4.18 | length 118.9
  Bottom Layer w10: R23.1@1128.07,2486.85 1128.03,2486.89 U4.18@1128.03,2605.71
NetR24_1: R24.1 U4.13 | length 119.5
  Bottom Layer w10: U4.13@1226.46,2605.71 1226.46,2488.46 R24.1@1228.07,2486.85
NetR25_1: R25.1 U4.19 | length 135.5
  Bottom Layer w10: R25.1@1068.07,2486.85 1068.07,2528.07 1108.35,2568.35 U4.19@1108.35,2605.71
NetR28_1: R28.1 U4.12 | length 136.2
  Bottom Layer w10: U4.12@1246.14,2605.71 1246.14,2568.86 1288.07,2526.93 R28.1@1288.07,2486.85
NetR31_1: R31.1 R33.2 TP23.1 | length 774
  Signal Layer w25: TP23.1@550,3300 685,3300 880,3105 880,2992.32 v1(783.07,2895.39)
  Bottom Layer w25: v1(783.07,2895.39) R33.2@831.54,2895.39 ; R31.1@828.07,2958.86 831.57,2955.35 R33.2@831.57,2895.35
NetR32_1: R32.1 R34.2 TP24.1 | length 517.2
  Bottom Layer w25: R34.2@1538.07,2903.86 R34.2@1529.57,2895.35 1529.57,3154.53 R32.1@1489.09,3195 1489.09,3275.23 1524.22,3310.35 TP24.1@1583.07,3310.35
NetR39_2: R39.2 U4.37 | length 149
  Bottom Layer w10: U4.37@1206.77,2834.06 1206.77,2917.56 R39.2@1253.07,2963.86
